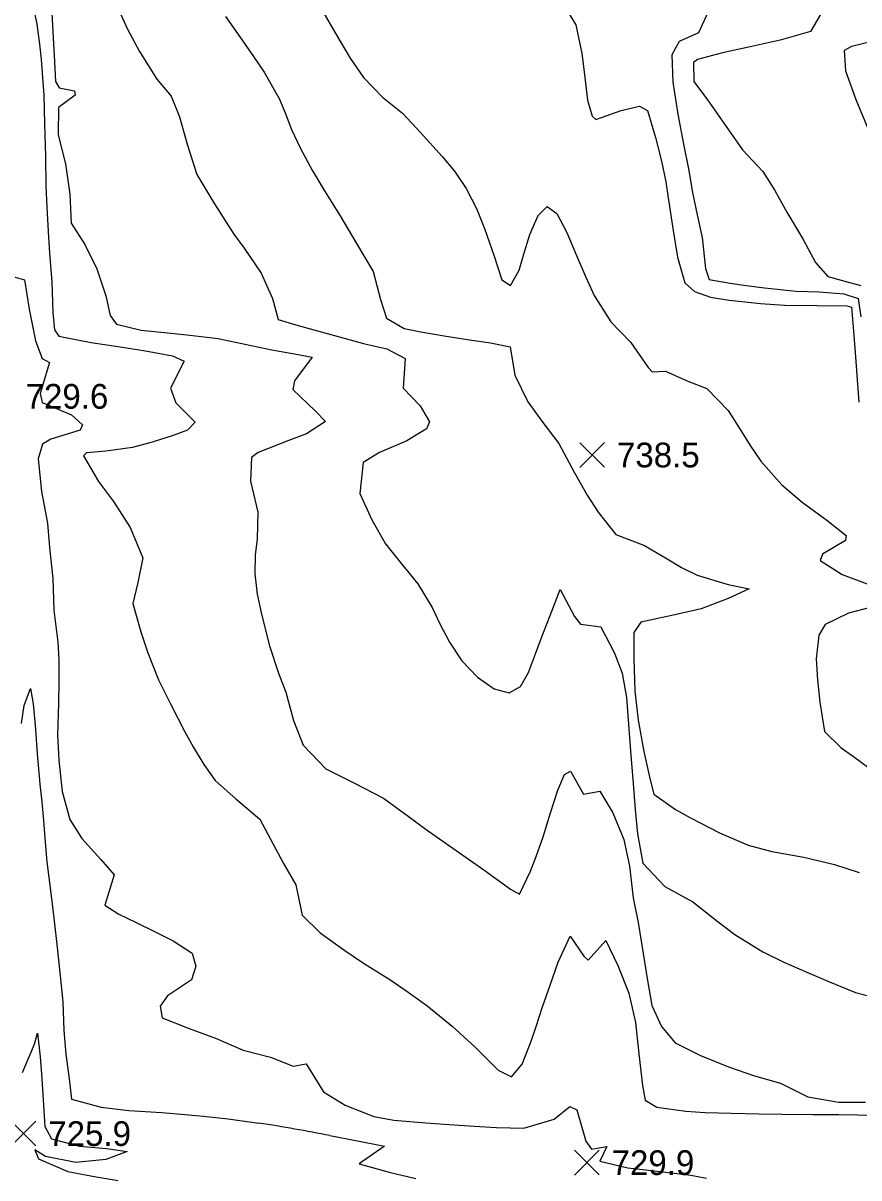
# Model space of a CAD drawing. Extents: x 2566079 to 2571326, y 424054 to 426896.
# Drawn here: x 2570104 to 2570611, y 425217 to 425917 of the extents above; entities that cross this region are included whole.
import ezdxf

# ---------------------------------------------------------------- set-up
doc = ezdxf.new("R2010")
doc.units = 0
for name, color, linetype in [('Contour_ADS_Major', 7, 'Continuous'), ('Contour_ADS_Minor', 7, 'Continuous'), ('Contour_ADS_Spot_Elevation', 7, 'Continuous')]:
    doc.layers.add(name, color=color, linetype=linetype)

# ---------------------------------------------------------------- blocks, each defined once
blk = doc.blocks.new('S750')
at = {"layer": 'Contour_ADS_Spot_Elevation'}
for p, q in [((-0.5, 0.498), (0.5, -0.498)), ((-0.498, -0.5), (0.498, 0.5))]:
    blk.add_line(p, q, dxfattribs=at)

msp = doc.modelspace()

# ---------------------------------------------------------------- linework, layer by layer
at = {"layer": 'Contour_ADS_Major'}
for points in [[(2570285.96, 425923.78), (2570293.55, 425910.88), (2570302.57, 425895.55), (2570310.72, 425883.74), (2570322.28, 425871.91), (2570334.28, 425862.26), (2570345.17, 425850.52), (2570358.34, 425835.89), (2570365.87, 425827.06), (2570373.04, 425816.61), (2570379.16, 425804.5), (2570384.03, 425792.4), (2570389.81, 425776.14), (2570394.68, 425761.24), (2570399.89, 425757.68), (2570405.17, 425767.09), (2570407.79, 425776.15), (2570411.64, 425788.59), (2570416.53, 425800.17), (2570422.11, 425805.63), (2570428.05, 425801.3), (2570434.07, 425789.93), (2570439.93, 425775.9), (2570445.45, 425762.86), (2570450.69, 425751.7), (2570460.8, 425735.63), (2570472.9, 425723.13), (2570483.33, 425708.05), (2570485.83, 425705.4), (2570493.86, 425705.81), (2570507.42, 425699.83), (2570519.02, 425695.4), (2570531.91, 425681.98), (2570538.59, 425671.41), (2570545.22, 425660.67), (2570551.69, 425651.32), (2570564.32, 425636.87)], [(2570096.58, 425763.58), (2570105.01, 425761.12), (2570107.88, 425743.36), (2570111.82, 425724.28), (2570115.86, 425713.52), (2570120.23, 425711.09), (2570114.61, 425692.27), (2570115.84, 425686.85), (2570133.52, 425679.34), (2570140.26, 425673.27), (2570138.83, 425670.04), (2570121.02, 425664.61), (2570116.05, 425661.65), (2570113.36, 425652.72), (2570115.45, 425632.85), (2570118.95, 425613.69), (2570120.27, 425598.86), (2570122.26, 425580.21), (2570122.95, 425560.89), (2570125.3, 425541.53), (2570125.94, 425531.11), (2570126, 425518.05), (2570125.67, 425504.43), (2570125.16, 425485.31), (2570125.94, 425469.93), (2570128.02, 425451.05), (2570132.65, 425434.04), (2570139.9, 425422.55), (2570151.35, 425409.77), (2570159.49, 425400.45), (2570153.72, 425382.15), (2570162.39, 425376.6), (2570172.37, 425371.85), (2570184.36, 425366.03), (2570195.27, 425360.54), (2570206.88, 425353.01), (2570208.96, 425345.21), (2570206.45, 425336.8), (2570191.79, 425327.09), (2570187.39, 425320.88), (2570188.57, 425313.83), (2570205.06, 425307.35), (2570220.92, 425301.43), (2570237.7, 425294.26), (2570254.23, 425289.9), (2570268.05, 425284.45), (2570275.91, 425285.83), (2570286.53, 425268.95), (2570299.65, 425260.94), (2570316.92, 425253.98), (2570329.03, 425251.82), (2570348.42, 425250.14), (2570362.57, 425249.14), (2570377.77, 425248.15), (2570391.37, 425247.36), (2570407.93, 425246.83), (2570426.35, 425252.37), (2570435.92, 425260.01)], [(2570564.32, 425636.87), (2570576.67, 425626.45), (2570591.7, 425615.39), (2570603.52, 425606.21), (2570603.01, 425603.13), (2570589.03, 425594.83), (2570587.64, 425591.01), (2570600.98, 425582.5), (2570617.88, 425576.37)], [(2570623.46, 425563.99), (2570604.85, 425559.08), (2570590.77, 425552.24), (2570586.82, 425545.83), (2570585.2, 425531.42), (2570585.95, 425518.77), (2570587.45, 425505.08), (2570590.24, 425487.44), (2570600.37, 425477.51), (2570607.87, 425472.23), (2570617.18, 425465.34)], [(2570435.92, 425260.01), (2570440.03, 425257.97), (2570445.55, 425238.98), (2570448.95, 425234.11), (2570458.26, 425235.86), (2570454.09, 425226.86), (2570471.04, 425222.8), (2570490.57, 425220.74), (2570509.27, 425218.48), (2570518.79, 425216.63)]]:
    msp.add_lwpolyline(points, dxfattribs=at)
at = {"layer": 'Contour_ADS_Minor'}
for points in [[(2570109.56, 425931.2), (2570112.66, 425916.27), (2570114.2, 425904.14), (2570115.16, 425894.73), (2570116.11, 425883.9), (2570116.82, 425873.1), (2570117.17, 425855.77), (2570117.91, 425835.98), (2570118.05, 425818.16), (2570118.69, 425805.27), (2570119.52, 425790.46), (2570120.35, 425777.29), (2570121.71, 425759.92), (2570122.27, 425741.43), (2570123.28, 425730.88), (2570125.9, 425727.12), (2570145.45, 425723.13), (2570163.15, 425720.58), (2570178.49, 425718.18), (2570194.79, 425715.14), (2570201.97, 425711.82), (2570193.62, 425695.55), (2570196.83, 425686.62), (2570208.58, 425674.83), (2570204.05, 425670.05), (2570194.66, 425666.53), (2570182.52, 425662.7)], [(2570121.38, 425926.74), (2570122.21, 425911.47), (2570123.04, 425897.22), (2570123.84, 425881.33), (2570126.08, 425877.59), (2570135.44, 425875.66), (2570135.8, 425873.09), (2570125.69, 425865.75), (2570125.57, 425848.99), (2570129.98, 425831.44), (2570132.67, 425813.16), (2570133.49, 425795.45), (2570141.6, 425782.65), (2570148.97, 425767.85), (2570154.49, 425751.42), (2570156.97, 425739.46), (2570160.97, 425734.24), (2570175.93, 425730.71), (2570193.78, 425728.82), (2570205.39, 425727.64), (2570222.55, 425725.7), (2570239.7, 425721.91), (2570255.13, 425718.78), (2570271.99, 425715.8), (2570279.64, 425714.27), (2570268.94, 425699.86), (2570267.78, 425694.8), (2570281.36, 425681.83), (2570287.61, 425675.31), (2570276.09, 425667.83), (2570264.72, 425663.63), (2570246.76, 425656.52), (2570242.79, 425653.41), (2570242.25, 425639.11), (2570246.67, 425620.36), (2570246.12, 425604.25), (2570245, 425594.23), (2570244.76, 425582.95), (2570246.21, 425570.7), (2570248.76, 425558.55), (2570253.64, 425539.25), (2570259.09, 425522.66), (2570263.53, 425511.2), (2570268.26, 425494.04), (2570274.01, 425479.05), (2570287.94, 425464.79), (2570305.16, 425456.06), (2570322.76, 425446.97), (2570337.83, 425435.97), (2570348.76, 425428.01), (2570360.78, 425419.43), (2570372.87, 425411.05), (2570383.77, 425403.58), (2570399.86, 425391.84), (2570405.22, 425388.75), (2570411.99, 425402.69), (2570415.51, 425411.6), (2570419.6, 425423.47), (2570424.04, 425437.98), (2570428.51, 425451.9), (2570432.69, 425461.3), (2570436.3, 425463.43), (2570444.06, 425449.38), (2570453.97, 425451.13), (2570461.87, 425438.02), (2570468.57, 425421.82), (2570472.07, 425405.7), (2570474.34, 425386.45), (2570477.33, 425371.52), (2570480.22, 425352.88), (2570482.8, 425337.56), (2570485.6, 425321.2), (2570491.48, 425308.47), (2570499.82, 425298.56), (2570515.05, 425291.01), (2570532.01, 425284.02), (2570547.75, 425278.54), (2570563.59, 425274.24), (2570580.12, 425265.84), (2570598.99, 425262.61), (2570615.06, 425262.62)], [(2570161.09, 425927.38), (2570167.47, 425913.06), (2570174.79, 425899.55), (2570185.31, 425882.84), (2570194.05, 425872.53), (2570199.17, 425859.98), (2570203.82, 425843.52), (2570209.65, 425825.11), (2570219.34, 425808.83), (2570225.55, 425798.89), (2570232.12, 425788.94), (2570238.28, 425780.31), (2570248.56, 425765.14), (2570255.44, 425749.84), (2570258.95, 425737.2), (2570269.68, 425733.84), (2570280.53, 425730.86), (2570293.04, 425727.41), (2570310.62, 425722.66), (2570324.9, 425719.27), (2570335.9, 425713.48), (2570334.69, 425695.61), (2570344.99, 425684.71), (2570350.75, 425675.08), (2570348.96, 425670.86), (2570336.89, 425663.57), (2570320.44, 425656.54), (2570310.54, 425650.36), (2570308.41, 425631.65), (2570315.84, 425615.76), (2570323.99, 425601.24), (2570333.67, 425588.98), (2570343.56, 425576.87), (2570352.27, 425562.48), (2570357, 425552.58), (2570362.76, 425541.49), (2570370.27, 425530.31), (2570379.82, 425520.28), (2570390.04, 425513.18), (2570399.14, 425510.9), (2570405.83, 425514.67), (2570410.75, 425523.17), (2570415.05, 425534.4), (2570419.55, 425546.45), (2570423.83, 425557.6), (2570430, 425573.47), (2570438.6, 425557.19), (2570442.33, 425552.36), (2570454.73, 425550.85), (2570462.91, 425534.84), (2570467.51, 425522.74), (2570470.29, 425508.02), (2570471.63, 425489.04), (2570472.87, 425472.99), (2570474.18, 425455.95), (2570475.45, 425440.16), (2570476.86, 425425.44), (2570480.16, 425407.57), (2570493.45, 425393.33), (2570510.51, 425384.09), (2570525.87, 425372.08), (2570535.98, 425364.22), (2570552.94, 425353.79), (2570565.67, 425347.62), (2570579.56, 425341.45), (2570592.3, 425336.04), (2570609.1, 425329.15), (2570627.8, 425324.26)], [(2570227.08, 425920.76), (2570235.72, 425908.43), (2570243.99, 425896.6), (2570250.55, 425887.02), (2570259.55, 425871.16), (2570263.12, 425862.41), (2570267.11, 425852.34), (2570272.42, 425840.7), (2570279.5, 425827.7), (2570287.01, 425815.18), (2570296.57, 425800), (2570306.39, 425783.3), (2570316.52, 425766.25), (2570321.04, 425749.23), (2570324.63, 425737.92), (2570335.29, 425731.78), (2570345.55, 425729.68), (2570359.7, 425727.31), (2570374.92, 425724.91), (2570387.63, 425722.93)], [(2570434.62, 425923.57), (2570439.52, 425915.71), (2570443.17, 425898.44), (2570444.46, 425887.22), (2570446.64, 425870.12), (2570449.33, 425860.45), (2570451.63, 425858.4), (2570466.99, 425863.79), (2570478.14, 425866.49), (2570482.88, 425863.89), (2570487.74, 425847.47), (2570491.42, 425833.05), (2570493.98, 425820.61), (2570495.54, 425810.86), (2570498.5, 425791.15), (2570501.21, 425774.83), (2570505.61, 425759.37), (2570511.45, 425754.18), (2570521.05, 425750.77), (2570532.51, 425748.82), (2570551.53, 425746.83), (2570566.03, 425745.79), (2570585.54, 425745.7), (2570603.83, 425745.5), (2570606.57, 425744.68), (2570607.89, 425730.09), (2570608.88, 425717.14), (2570610.34, 425697.88), (2570611.16, 425687.12)], [(2570520.7, 425925.78), (2570513.95, 425910.97), (2570502.12, 425905.58), (2570497.77, 425897.58), (2570498.31, 425881.02), (2570501.41, 425861.69), (2570504.73, 425843.48), (2570507.78, 425828.49), (2570510.27, 425814.15), (2570513.11, 425800.56), (2570516.08, 425786.92), (2570518.18, 425768.13), (2570520.34, 425761.38), (2570533, 425759.15), (2570542.74, 425757.79), (2570553.98, 425756.26), (2570573.03, 425754.33), (2570586.92, 425753.83), (2570601.92, 425752.67), (2570610.66, 425749.85), (2570612.3, 425738.73)], [(2570587.85, 425922.07), (2570581.81, 425911.8), (2570563.42, 425906.56), (2570545.18, 425902.47), (2570528.37, 425898.82), (2570513.35, 425894.68), (2570510.8, 425893.02), (2570511.13, 425881.47), (2570519.29, 425870.35), (2570529.3, 425856.22), (2570540.64, 425840.07), (2570552.86, 425826.86), (2570560.13, 425815.31), (2570567.45, 425802.12), (2570577.36, 425785.63), (2570584.8, 425771.61), (2570592.29, 425763.26), (2570606.35, 425759.46), (2570612.39, 425757.79)], [(2570619.15, 425905.66), (2570606.74, 425902.67), (2570602.31, 425900.24), (2570603.12, 425887.78), (2570609.25, 425870.45), (2570616.68, 425852.44)], [(2570387.63, 425722.93), (2570399.67, 425720.65), (2570402.57, 425703.42), (2570410.42, 425687.29), (2570419.44, 425674.72), (2570429.13, 425662.01), (2570438.56, 425644.52), (2570446.31, 425630.67), (2570452.98, 425620.41), (2570463.78, 425606.88), (2570481.21, 425600.13), (2570494.89, 425591.96), (2570503.48, 425586.82), (2570513.14, 425582.08), (2570531.79, 425576.49), (2570544.57, 425573.77), (2570531.86, 425568.04), (2570515.43, 425561.67), (2570497.74, 425557.78), (2570478.88, 425553.62), (2570474.59, 425547.35), (2570474.56, 425531.39), (2570475.16, 425511.99), (2570477.24, 425494.15), (2570480.71, 425475.33), (2570484.39, 425458.83), (2570486.81, 425449.35), (2570499.91, 425440.16), (2570508.99, 425435.14), (2570526.61, 425426.02), (2570543.9, 425418.39), (2570558.3, 425414.57), (2570577.84, 425411.26), (2570596.26, 425406.84), (2570611.38, 425401.99)], [(2570182.52, 425662.7), (2570170.6, 425659.57), (2570154.34, 425657.24), (2570142.72, 425656.25), (2570140.91, 425654.46), (2570149.97, 425638.89), (2570159.1, 425626.81), (2570169.19, 425610.98), (2570176.91, 425592.6), (2570173.83, 425577.67), (2570170.88, 425564.93), (2570175.7, 425547.7), (2570179.83, 425534.97), (2570186.39, 425518.7), (2570193.78, 425503.76), (2570202.29, 425487.22), (2570207.36, 425478.16), (2570213.84, 425467.39), (2570220.81, 425457.6), (2570233.27, 425446.49), (2570247.8, 425434.2), (2570254.36, 425422.14), (2570262.19, 425407.29), (2570269.58, 425394.39), (2570273.49, 425375.96), (2570284.4, 425365.25), (2570299.47, 425354.64), (2570310.6, 425346.99), (2570326.6, 425337.02), (2570337.75, 425329.4), (2570349.16, 425321.19), (2570364.44, 425308.84), (2570378.46, 425296.07), (2570392.47, 425282.11), (2570400.45, 425278.05), (2570406.99, 425285.62), (2570412.47, 425299.75), (2570415.44, 425308.61), (2570419.14, 425319.81), (2570423.81, 425333.6), (2570428.74, 425347.46), (2570436, 425363.25), (2570444.29, 425351.16), (2570447.05, 425348.8), (2570457.68, 425360.69), (2570464.85, 425345.54), (2570471.53, 425328.68), (2570475.64, 425310.89), (2570477.7, 425291.95), (2570479.94, 425272.88), (2570481.5, 425263.97), (2570488.53, 425259.62), (2570506.22, 425257.15), (2570517.87, 425256.47), (2570533.69, 425255.97), (2570550.54, 425255.64), (2570564.39, 425255.46), (2570583.27, 425255.27), (2570599.01, 425255.19), (2570610.4, 425255.01), (2570623.39, 425254.68)], [(2570103.25, 425492.24), (2570104.91, 425503.07), (2570108.67, 425513.44), (2570110.38, 425504.18), (2570111.82, 425488.76), (2570112.87, 425473.79), (2570114.39, 425455.41), (2570115.57, 425444.7), (2570116.6, 425433.42), (2570117.73, 425420.24), (2570118.71, 425408.33), (2570121.12, 425389.46), (2570123.12, 425372.6), (2570124.82, 425356.34), (2570126.81, 425339.31), (2570128.31, 425323.41), (2570128.86, 425306.06), (2570130.2, 425291.75)], [(2570103.96, 425280.65), (2570111.1, 425297.81), (2570112.97, 425304.51), (2570114.7, 425290.15), (2570115.4, 425279.64), (2570116.2, 425267.32), (2570117.49, 425247.91), (2570121.51, 425240.37), (2570138.54, 425236.05), (2570154.93, 425234.67), (2570167.28, 425232.75), (2570154.34, 425228.02), (2570136.32, 425226.02), (2570117.83, 425229.73), (2570111.29, 425233.81), (2570113.58, 425228.23), (2570131.42, 425220.61), (2570148.6, 425217.44), (2570161.82, 425215.15)], [(2570130.2, 425291.75), (2570132.09, 425276.73), (2570133.66, 425264.41), (2570151.58, 425259.73), (2570168.39, 425257.59), (2570188.3, 425256.33), (2570202.31, 425255.16), (2570213.66, 425254.17), (2570228.65, 425252.57), (2570247.32, 425250.02)], [(2570290.34, 425242.45), (2570307.16, 425239.2), (2570323.47, 425236), (2570308, 425225.37), (2570326.28, 425220.18), (2570342.36, 425216.42)]]:
    msp.add_lwpolyline(points, dxfattribs=at)
for centre, radius, start, end in [((2570094.93, 424271.89), 989.93, 79.87071, 81.14473), ((2569946.24, 423440.95), 1834.07, 79.18639, 79.86339)]:
    msp.add_arc(centre, radius, start, end, dxfattribs=at)

# ---------------------------------------------------------------- block references
at = {"layer": 'Contour_ADS_Spot_Elevation', "xscale": 15, "yscale": 15}
for p in [(2570449.4, 425654.99), (2570104.5, 425243.62), (2570446.13, 425226.02)]:
    msp.add_blockref('S750', p, dxfattribs=at)

# ---------------------------------------------------------------- texts
at = {"layer": 'Contour_ADS_Spot_Elevation'}
for s, p in [('729.6', (2570105.76, 425683.05)), ('738.5', (2570464.4, 425647.49)), ('725.9', (2570119.5, 425236.12)), ('729.9', (2570461.13, 425218.52))]:
    msp.add_text(s, height=15, dxfattribs=at).set_placement(p)

doc.saveas('drawing.dxf')
